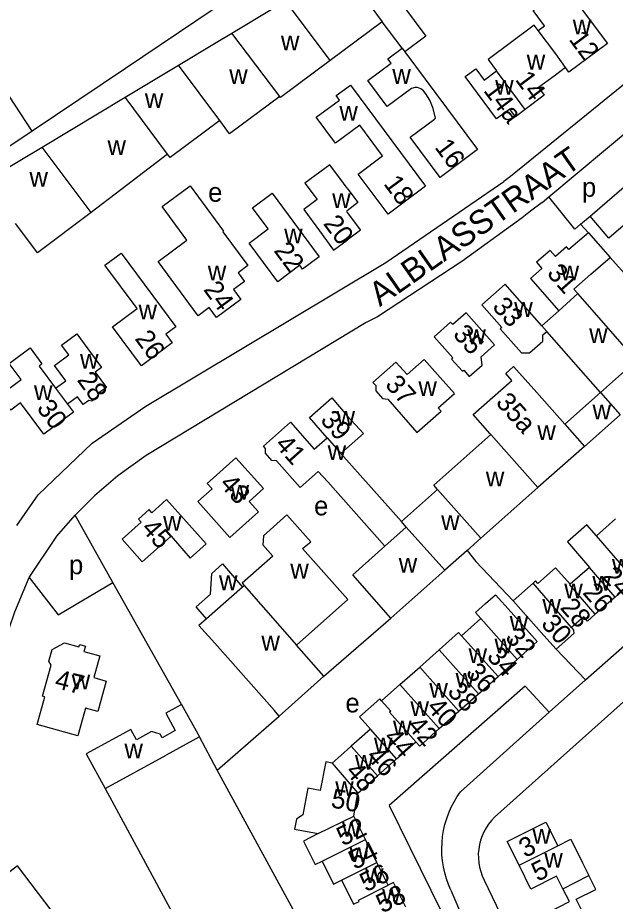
# Model space of a CAD drawing. Extents: x 156721 to 158827, y 386657 to 388950.
# Drawn here: x 157431.2 to 157555.9, y 387710.2 to 387894.5 of the extents above; entities that cross this region are included whole.
import ezdxf

# ---------------------------------------------------------------- set-up
doc = ezdxf.new("R2010")
doc.units = 0
for name, color, linetype in [('BLT_Basislijn', 7, 'Continuous'), ('BLT_Bebouwing', 7, 'Continuous'), ('BLT_Centroide', 7, 'Continuous'), ('BLT_Hoogspanningsmast_en_leidingen', 7, 'Continuous'), ('BLT_Huisnummer', 7, 'Continuous'), ('BLT_Huisnummer_ tussenligend', 7, 'Continuous'), ('BLT_Onderverdeling_panden', 7, 'Continuous'), ('BLT_Straatnaam', 7, 'Continuous')]:
    doc.layers.add(name, color=color, linetype=linetype)

msp = doc.modelspace()

# ---------------------------------------------------------------- linework, layer by layer
at = {"layer": 'BLT_Basislijn'}
for p, q in [((157542.05, 387857.12), (157567.63, 387878.57)), ((157540.64, 387855.93), (157538.26, 387854.12)), ((157540.64, 387855.93), (157542.05, 387857.12)), ((157548.7, 387851.47), (157550.68, 387853.1)), ((157550.32, 387849.62), (157548.7, 387851.47)), ((157563.41, 387834.83), (157554.84, 387844.52)), ((157549.68, 387756.41), (157593.29, 387794.87)), ((157433.63, 387777.77), (157439.68, 387769.95)), ((157439.68, 387769.95), (157451.11, 387776.75)), ((157465.46, 387751.28), (157451.11, 387776.75)), ((157495.15, 387757.16), (157509.09, 387769.3)), ((157570.53, 387763.42), (157530.74, 387727.79)), ((157549.68, 387756.41), (157543.57, 387762.81)), ((157549.68, 387756.41), (157542.13, 387749.65)), ((157472.87, 387737.57), (157485.81, 387748.88)), ((157542.13, 387749.65), (157523.63, 387733.1)), ((157521.63, 387712.57), (157524.08, 387706.86))]:
    msp.add_line(p, q, dxfattribs=at)
for points in [[(157589.35, 387906.27), (157534.05, 387861.36), (157532.64, 387860.36)], [(157431.05, 387788.63), (157435.53, 387794.97), (157446.77, 387805.76), (157457.97, 387813.49), (157508.05, 387843.42), (157531.57, 387859.59), (157532.64, 387860.36)], [(157548.7, 387851.47), (157547.46, 387850.41), (157542.05, 387857.12)], [(157538.26, 387854.12), (157536.47, 387852.76), (157523.91, 387843.64), (157506.32, 387832.11), (157503.93, 387830.93), (157458.03, 387803.21), (157452.13, 387798.96), (157447.3, 387794.79), (157443.27, 387790.75)], [(157433.63, 387777.77), (157439.41, 387786.37), (157443.27, 387790.75)], [(157451.11, 387776.75), (157443.27, 387790.75)], [(157525.01, 387783.41), (157526.82, 387781.11), (157534.63, 387772.92)], [(157448.94, 387641.7), (157448.24, 387641.22), (157437.86, 387655.06), (157417.27, 387677.44), (157412.48, 387683.06), (157411.05, 387686.03), (157410.8, 387690.3), (157412, 387696.4), (157429.48, 387767.11), (157430.68, 387770.62), (157433.63, 387777.77)], [(157542.13, 387749.65), (157537.09, 387755.14), (157508.77, 387730.24), (157526.13, 387694.91)], [(157521.63, 387712.57), (157521.13, 387713.74), (157520.71, 387714.94), (157520.36, 387716.17), (157520.08, 387717.41), (157519.89, 387718.67), (157519.77, 387719.94), (157519.74, 387721.22), (157519.78, 387722.49), (157519.91, 387723.76), (157520.11, 387725.02), (157520.39, 387726.26), (157520.75, 387727.48), (157521.19, 387728.68), (157521.7, 387729.85), (157522.28, 387730.98), (157522.93, 387732.08), (157523.63, 387733.1)], [(157530.74, 387727.79), (157530.09, 387727.1), (157529.5, 387726.36), (157528.97, 387725.57), (157528.52, 387724.74), (157528.13, 387723.87), (157527.82, 387722.98), (157527.59, 387722.06), (157527.43, 387721.12), (157527.35, 387720.18), (157527.36, 387719.23), (157527.44, 387718.29), (157527.6, 387717.36), (157527.84, 387716.44), (157528.16, 387715.55), (157528.58, 387714.63)], [(157528.58, 387714.63), (157545.48, 387679.5), (157547.3, 387675.81)]]:
    msp.add_lwpolyline(points, dxfattribs=at)
at = {"layer": 'BLT_Bebouwing'}
for p, q in [((157475.95, 387891.28), (157484.49, 387896.4)), ((157507.31, 387893.66), (157496.41, 387885.58)), ((157539, 387892.94), (157529.37, 387885.78)), ((157539.81, 387891.79), (157539, 387892.94)), ((157472.34, 387889.11), (157475.95, 387891.28)), ((157464.8, 387884.59), (157472.34, 387889.11)), ((157512.01, 387887.37), (157527.18, 387867)), ((157496.41, 387885.58), (157486.07, 387877.86)), ((157529.37, 387885.78), (157531.16, 387883.38)), ((157459.6, 387881.47), (157464.8, 387884.59)), ((157453.66, 387877.9), (157459.6, 387881.47)), ((157436.38, 387867.53), (157453.66, 387877.9)), ((157486.07, 387877.86), (157485.94, 387878.04)), ((157473.4, 387873.07), (157463.03, 387865.36)), ((157424.3, 387860.28), (157436.38, 387867.53)), ((157462.54, 387866.01), (157446.57, 387853.84)), ((157463.03, 387865.36), (157462.54, 387866.01)), ((157431.25, 387850.97), (157430.82, 387851.55)), ((157550.32, 387849.62), (157554.84, 387844.52)), ((157544.14, 387833.4), (157540.57, 387830.25)), ((157552.86, 387816.36), (157541.61, 387829.07)), ((157435.71, 387821.86), (157439.16, 387817.24)), ((157439.16, 387817.24), (157441.27, 387818.8)), ((157443.73, 387815.45), (157441.63, 387813.93)), ((157545.37, 387809.73), (157552.86, 387816.36)), ((157552.86, 387816.36), (157556.97, 387811.71)), ((157556.97, 387811.71), (157549.49, 387805.09)), ((157549.49, 387805.09), (157539.79, 387796.5)), ((157498.64, 387803.63), (157511.3, 387789.42)), ((157539.79, 387796.5), (157527.88, 387785.95)), ((157507.84, 387784.29), (157512.3, 387788.28)), ((157527.88, 387785.95), (157525.01, 387783.41)), ((157525.01, 387783.41), (157520.33, 387779.26)), ((157473.98, 387780.58), (157478.17, 387775.78)), ((157520.33, 387779.26), (157509.09, 387769.3)), ((157550.51, 387779.88), (157546.5, 387776.34)), ((157538.8, 387776.6), (157534.63, 387772.92)), ((157559.93, 387777.26), (157555.88, 387773.67)), ((157478.53, 387776.1), (157478.17, 387775.78)), ((157489.39, 387763.66), (157500.12, 387773.18)), ((157523.83, 387765.6), (157527.86, 387769.19)), ((157543.57, 387762.81), (157541.02, 387765.68)), ((157515.14, 387759.1), (157519.18, 387762.69)), ((157531.46, 387757.15), (157535.44, 387760.69)), ((157495.15, 387757.16), (157487.09, 387750)), ((157527.38, 387753.52), (157531.46, 387757.15)), ((157465.46, 387751.28), (157469.16, 387744.51)), ((157485.81, 387748.88), (157484.82, 387750)), ((157487.09, 387750), (157485.81, 387748.88)), ((157519.21, 387746.25), (157523.29, 387749.88)), ((157504.85, 387746.13), (157500.85, 387742.57)), ((157510.3, 387739.98), (157514.29, 387743.53)), ((157506.31, 387736.43), (157510.3, 387739.98)), ((157502.23, 387732.8), (157506.31, 387736.43)), ((157503.83, 387723.11), (157501.4, 387727.99)), ((157506.21, 387718.33), (157503.83, 387723.11)), ((157508.56, 387713.61), (157506.21, 387718.33))]:
    msp.add_line(p, q, dxfattribs=at)
for points in [[(157409.42, 387908.81), (157414.45, 387912.18), (157410.44, 387918.15), (157424.45, 387927.56), (157428.45, 387921.62), (157446.74, 387933.97), (157472.03, 387896.19), (157453.77, 387883.92)], [(157529.73, 387905.37), (157532.07, 387902.23), (157527.69, 387898.97), (157520.53, 387908.6), (157509.29, 387900.24), (157516.43, 387890.66), (157512.01, 387887.37)], [(157539.81, 387891.79), (157541.17, 387892.8), (157538.8, 387895.99), (157545.21, 387900.76), (157547.6, 387897.55), (157547.84, 387897.73), (157551.3, 387893.1)], [(157511.45, 387888.12), (157507.31, 387893.66)], [(157551.3, 387893.1), (157554.29, 387889.09), (157546.23, 387883.12), (157545.54, 387884.09)], [(157527.18, 387867), (157519.36, 387861.18), (157513.12, 387869.55), (157518.2, 387873.34), (157518.43, 387873.51), (157517.92, 387875.55), (157517.21, 387877.33), (157516.4, 387878.64), (157515.88, 387879.23), (157515.33, 387879.66), (157514.65, 387879.92), (157514.15, 387879.92), (157513.44, 387879.74), (157508.36, 387875.96), (157504.32, 387881.39), (157509.18, 387885.01), (157508.5, 387885.93), (157511.45, 387888.12)], [(157453.77, 387883.92), (157434.24, 387870.82)], [(157537.15, 387875.36), (157535.1, 387873.84), (157533.92, 387875.44), (157531.13, 387873.38), (157524.58, 387882.2), (157526.82, 387883.86), (157528.6, 387881.47), (157531.16, 387883.38)], [(157545.54, 387884.09), (157543.16, 387882.32), (157539.92, 387879.91), (157541.11, 387878.31), (157537.15, 387875.36)], [(157500.65, 387880.45), (157516.36, 387859.35), (157508.55, 387853.53), (157502.31, 387861.9), (157507.39, 387865.69), (157502.62, 387872.09), (157497.54, 387868.3), (157493.49, 387873.73), (157498.37, 387877.33)], [(157498.37, 387877.33), (157497.69, 387878.26), (157500.65, 387880.45)], [(157485.94, 387878.04), (157475.47, 387870.29), (157473.4, 387873.07)], [(157434.24, 387870.82), (157415.87, 387858.5)], [(157500, 387858.94), (157499.24, 387859.96), (157496.37, 387863.84), (157491.16, 387860.02), (157493.74, 387856.55), (157490.94, 387854.48), (157494.2, 387850.05), (157497.17, 387846.03), (157500, 387848.13)], [(157467.25, 387859.45), (157474.22, 387849.97), (157474.06, 387849.86), (157479.26, 387842.79), (157477.23, 387841.29), (157478.56, 387839.47), (157476.28, 387837.79), (157477.82, 387835.7), (157472.75, 387831.96), (157471.21, 387834.06), (157468.89, 387832.35), (157460.55, 387843.63), (157466.57, 387848.07), (157461.37, 387855.1), (157467.25, 387859.45)], [(157550.68, 387853.1), (157557.8, 387859.23)], [(157484.32, 387857.88), (157494.14, 387844.63), (157490.69, 387842.08), (157490.11, 387842.86), (157485.51, 387839.45), (157479.55, 387847.49), (157483.54, 387850.44), (157480.25, 387854.87), (157484.32, 387857.88)], [(157500, 387858.94), (157502.22, 387855.95), (157500, 387854.25)], [(157446.57, 387853.84), (157435.38, 387845.46), (157431.25, 387850.97)], [(157500, 387854.25), (157499.83, 387854.12), (157500, 387853.89)], [(157500, 387853.89), (157502.79, 387850.2), (157500, 387848.13)], [(157558.54, 387851.95), (157554.59, 387848.55), (157550.68, 387853.1)], [(157550.32, 387849.62), (157546.22, 387846.17), (157545.75, 387846.69), (157543.44, 387844.69)], [(157452.81, 387845.41), (157464.22, 387830.03), (157462.14, 387828.48), (157463.49, 387826.67), (157457.08, 387821.91), (157451.06, 387830.02), (157456.2, 387833.83), (157449.46, 387842.91), (157452.81, 387845.41)], [(157543.44, 387844.69), (157542.31, 387845.96), (157539.48, 387843.5), (157540.59, 387842.22), (157538.21, 387840.13), (157544.14, 387833.4)], [(157550.83, 387841.03), (157554.84, 387844.52)], [(157548.08, 387836.97), (157547.25, 387837.91), (157550.83, 387841.03)], [(157540.57, 387830.25), (157532.92, 387838.9), (157528.06, 387834.59), (157532.23, 387829.87), (157531.93, 387829.6), (157536.36, 387824.59), (157538.04, 387824.59), (157540.79, 387827.02), (157540.78, 387828.33), (157541.61, 387829.07)], [(157552.86, 387816.36), (157560.37, 387822.98), (157548.08, 387836.97)], [(157528.1, 387829.24), (157524.78, 387832.98), (157522, 387830.5), (157521.58, 387830.98), (157518.16, 387827.94), (157522.05, 387823.56), (157521.78, 387823.32), (157524.06, 387820.76), (157524.32, 387820.99), (157525.47, 387819.69), (157528.12, 387822.03), (157527.92, 387823.8), (157530.72, 387826.28), (157528.1, 387829.24)], [(157441.27, 387818.8), (157438.94, 387821.97), (157441.91, 387824.18), (157440.42, 387826.19), (157443.59, 387828.54), (157448.77, 387821.55), (157447.42, 387820.55), (157449.77, 387817.4), (157448.13, 387816.19), (157448.07, 387815.53), (157446.73, 387814.52), (157446.1, 387814.66), (157444.94, 387813.81), (157443.73, 387815.45)], [(157441.63, 387813.93), (157442.89, 387812.24), (157436.72, 387807.64), (157431.83, 387814.19), (157429.82, 387812.69), (157427.53, 387815.76), (157431.98, 387819.08), (157429.5, 387822.41), (157433.83, 387825.65), (157436.32, 387822.31), (157435.71, 387821.86)], [(157519.39, 387819.48), (157516.08, 387823.24), (157512.49, 387820.07), (157510.17, 387822.68), (157505.36, 387818.44), (157505.95, 387817.77), (157505.98, 387816.7), (157507.38, 387815.12), (157508.45, 387814.95), (157514.55, 387808.03), (157519.59, 387812.47), (157519, 387813.17), (157522.37, 387816.13), (157519.39, 387819.48)], [(157529.96, 387807.55), (157529.83, 387807.7), (157526.25, 387811.72), (157534.34, 387818.87), (157533.07, 387820.31), (157534.71, 387821.77), (157539.53, 387816.32), (157545.37, 387809.73)], [(157495.83, 387806.87), (157492.12, 387811.13), (157496.79, 387815.26), (157500, 387811.48)], [(157500, 387811.48), (157503.41, 387807.8), (157498.64, 387803.63)], [(157507.84, 387784.29), (157495.97, 387797.69), (157493.97, 387799.9), (157490.18, 387796.56), (157485.26, 387802.11), (157484.29, 387802.16), (157482.95, 387803.67), (157482.98, 387804.67), (157482.55, 387805.18), (157488.18, 387810.15), (157493.11, 387804.5), (157495.83, 387806.87)], [(157518.86, 387796.09), (157518.06, 387797), (157529.96, 387807.55)], [(157476.78, 387802.72), (157470.81, 387797.38), (157471.81, 387796.26), (157468.82, 387793.59), (157475.5, 387786.12), (157481.47, 387791.46), (157479.53, 387793.64), (157482.51, 387796.3), (157476.78, 387802.72)], [(157511.3, 387789.42), (157518.86, 387796.09)], [(157453.07, 387785.78), (157457.25, 387781.04), (157463.27, 387786.35), (157467.26, 387781.83), (157470.58, 387784.76), (157462.33, 387794.01), (157459.26, 387791.28), (157458.68, 387791.93), (157456.43, 387789.93), (157457.01, 387789.28), (157453.07, 387785.78)], [(157500.12, 387773.18), (157490.69, 387783.78), (157492.39, 387785.2), (157490.74, 387787.05), (157487.43, 387790.8), (157482.51, 387786.48), (157482.38, 387784.55), (157484.46, 387782.18), (157478.11, 387776.6), (157478.53, 387776.1)], [(157512.3, 387788.28), (157511.3, 387789.42)], [(157555.99, 387789.97), (157552.01, 387786.42)], [(157552.01, 387786.42), (157549.99, 387788.76), (157545.94, 387785.18), (157550.51, 387779.88)], [(157509.09, 387769.3), (157501.14, 387778.3), (157507.84, 387784.29)], [(157470.64, 387769.18), (157468.47, 387771.66), (157471.5, 387774.3), (157471.73, 387778.62), (157473.98, 387780.58)], [(157546.5, 387776.34), (157543.48, 387779.76), (157539.8, 387776.5), (157539.31, 387777.05), (157538.8, 387776.6)], [(157527.86, 387769.19), (157526.74, 387770.44), (157528.85, 387772.31), (157530.95, 387774.18), (157534.17, 387770.55), (157536.3, 387768.15), (157539.63, 387764.42), (157535.44, 387760.69)], [(157534.63, 387772.92), (157539.42, 387767.49), (157541.02, 387765.68)], [(157555.88, 387773.67), (157551.76, 387770.12)], [(157470.64, 387769.18), (157469.04, 387767.79), (157472.36, 387764.05), (157484.82, 387750)], [(157551.76, 387770.12), (157550.12, 387768.68), (157549.34, 387769.57), (157546.8, 387767.33)], [(157546.8, 387767.33), (157547.24, 387766.81), (157547.28, 387766.08), (157543.57, 387762.81)], [(157519.18, 387762.69), (157523.23, 387766.28), (157523.83, 387765.6)], [(157441.03, 387764.15), (157444.04, 387763.34), (157444.19, 387763.79), (157445.38, 387763.46), (157445.06, 387762.32), (157448.37, 387761.4), (157447.12, 387756.88), (157449.73, 387756.16), (157447.97, 387749.81), (157445.37, 387750.53), (157443.77, 387744.75), (157435.32, 387747.08), (157436.91, 387752.85), (157436.43, 387752.99), (157438.21, 387759.5), (157437.74, 387760.34), (157438.41, 387762.76), (157441.03, 387764.15)], [(157495.15, 387757.16), (157489.39, 387763.66)], [(157511, 387755.42), (157515.14, 387759.1)], [(157511, 387755.42), (157507.18, 387752.03)], [(157507.18, 387752.03), (157506.78, 387752.48), (157502.55, 387748.72), (157504.85, 387746.13)], [(157523.29, 387749.88), (157523.43, 387750), (157527.38, 387753.52)], [(157465.46, 387751.28), (157462.13, 387749.47), (157464.11, 387745.84), (157461.36, 387744.34), (157460.96, 387745.08), (157459.16, 387745.62), (157456.03, 387743.92), (157454.86, 387746.07), (157445.55, 387741), (157449.47, 387733.79)], [(157514.29, 387743.53), (157515.12, 387742.61), (157519.21, 387746.25)], [(157469.16, 387744.51), (157462.2, 387740.73)], [(157472.87, 387737.57), (157469.16, 387744.51)], [(157500.85, 387742.57), (157500, 387741.82), (157496.89, 387739.05)], [(157496.89, 387739.05), (157495.54, 387739.32), (157494.37, 387733.34), (157491.81, 387733.84), (157490.72, 387728.29), (157489.41, 387727.4), (157489, 387725.29), (157493.95, 387724.35)], [(157502.52, 387683.28), (157500, 387687.91), (157472.87, 387737.57)], [(157449.47, 387733.79), (157475.61, 387685.56), (157480.9, 387688.44), (157499.58, 387654.16), (157500, 387654.39), (157504.24, 387656.7), (157510.89, 387644.49)], [(157501.4, 387727.99), (157501.36, 387728.08), (157502.23, 387732.8)], [(157535.84, 387717.75), (157533.36, 387722.72), (157541.43, 387726.75), (157543.92, 387721.78)], [(157493.95, 387724.35), (157490.85, 387722.79), (157493.33, 387717.89), (157494.74, 387718.6)], [(157543.92, 387721.78), (157546.62, 387723.18), (157549.08, 387718.26), (157550.4, 387715.61)], [(157494.74, 387718.6), (157497.16, 387713.79), (157498.84, 387714.64)], [(157545.01, 387712.85), (157543.64, 387715.51), (157538.32, 387712.79), (157535.84, 387717.75)], [(157550.22, 387705.81), (157547.78, 387710.69), (157551.84, 387712.72), (157551.31, 387713.79), (157550.4, 387715.61)], [(157498.84, 387714.64), (157500, 387712.33), (157501.34, 387709.66), (157502.46, 387710.22)], [(157512.22, 387709.04), (157509.67, 387714.15), (157508.56, 387713.61)], [(157542.18, 387701.79), (157539.65, 387706.74), (157546.37, 387710.18), (157545.01, 387712.85)]]:
    msp.add_lwpolyline(points, dxfattribs=at)
at = {"layer": 'BLT_Hoogspanningsmast_en_leidingen'}
msp.add_lwpolyline([(157428.67, 387700.66), (157438.47, 387708.12), (157431.24, 387717.61), (157421.44, 387710.16)], close=True, dxfattribs=at)
at = {"layer": 'BLT_Onderverdeling_panden'}
for p, q in [((157434.24, 387870.82), (157409.42, 387908.81)), ((157498.86, 387905.05), (157507.31, 387893.66)), ((157496.41, 387885.58), (157487.14, 387897.99)), ((157485.94, 387878.04), (157475.95, 387891.28)), ((157511.45, 387888.12), (157512.01, 387887.37)), ((157473.4, 387873.07), (157464.8, 387884.59)), ((157537.15, 387875.36), (157531.16, 387883.38)), ((157462.54, 387866.01), (157453.66, 387877.9)), ((157446.57, 387853.84), (157436.38, 387867.53)), ((157544.14, 387833.4), (157548.08, 387836.97)), ((157540.57, 387830.25), (157541.61, 387829.07)), ((157439.16, 387817.24), (157441.63, 387813.93)), ((157545.37, 387809.73), (157549.49, 387805.09)), ((157495.83, 387806.87), (157498.64, 387803.63)), ((157529.96, 387807.55), (157539.79, 387796.5)), ((157518.86, 387796.09), (157527.88, 387785.95)), ((157512.3, 387788.28), (157520.33, 387779.26)), ((157559.93, 387777.26), (157552.01, 387786.42)), ((157555.88, 387773.67), (157550.51, 387779.88)), ((157546.8, 387767.33), (157538.8, 387776.6)), ((157478.17, 387775.78), (157470.64, 387769.18)), ((157478.53, 387776.1), (157489.39, 387763.66)), ((157535.44, 387760.69), (157527.86, 387769.19)), ((157531.46, 387757.15), (157523.83, 387765.6)), ((157527.38, 387753.52), (157519.18, 387762.69)), ((157523.29, 387749.88), (157515.14, 387759.1)), ((157519.21, 387746.25), (157511, 387755.42)), ((157514.29, 387743.53), (157508.82, 387749.67)), ((157510.3, 387739.98), (157504.85, 387746.13)), ((157506.31, 387736.43), (157500.85, 387742.57)), ((157449.47, 387733.79), (157462.21, 387740.73)), ((157496.89, 387739.05), (157502.23, 387732.8)), ((157493.95, 387724.35), (157501.4, 387727.99)), ((157494.74, 387718.6), (157503.83, 387723.11)), ((157535.84, 387717.75), (157543.92, 387721.78)), ((157498.84, 387714.64), (157506.21, 387718.33)), ((157545.01, 387712.85), (157550.4, 387715.61))]:
    msp.add_line(p, q, dxfattribs=at)
for points in [[(157545.54, 387884.09), (157543.49, 387886.97), (157539.81, 387891.79)], [(157551.76, 387770.12), (157546.41, 387776.24), (157546.5, 387776.34)], [(157507.18, 387752.03), (157509.08, 387749.9), (157508.82, 387749.67)], [(157502.46, 387710.22), (157502.32, 387710.49), (157508.56, 387713.61)]]:
    msp.add_lwpolyline(points, dxfattribs=at)

# ---------------------------------------------------------------- texts
at = {"layer": 'BLT_Centroide'}
for s, p in [('w', (157547.05, 387891)), ('w', (157486.17, 387887.67)), ('w', (157537.45, 387883.69)), ('w', (157475.38, 387880.67)), ('w', (157509.41, 387880.7)), ('w', (157530.86, 387878.45)), ('w', (157457.78, 387875.68)), ('w', (157498.36, 387873.04)), ('w', (157449.98, 387865.88)), ('w', (157433.7, 387859.25)), ('e', (157470.98, 387856.11)), ('p', (157548.97, 387857.15)), ('w', (157496.86, 387854.81)), ('w', (157486.84, 387847.45)), ('w', (157470.91, 387839.72)), ('w', (157544.52, 387839.72)), ('w', (157456.47, 387831.59)), ('w', (157534.84, 387832.11)), ('w', (157550.47, 387826.66)), ('w', (157525.05, 387826.41)), ('w', (157444.25, 387821.3)), ('w', (157514.85, 387815.62)), ('w', (157434.65, 387814.75)), ('w', (157551.17, 387810.72)), ('w', (157497.77, 387809.39)), ('w', (157539.66, 387806.42)), ('w', (157495.91, 387802.27)), ('w', (157528.92, 387796.75)), ('w', (157475.67, 387794)), ('e', (157493.08, 387790.72)), ('w', (157461.58, 387787.53)), ('w', (157519.59, 387787.69)), ('w', (157510.74, 387778.78)), ('p', (157441.96, 387778.44)), ('w', (157488.12, 387777.55)), ('w', (157555.23, 387778.56)), ('w', (157473.25, 387775.12)), ('w', (157545.28, 387773.41)), ('w', (157551.14, 387775.03)), ('w', (157540.72, 387770.2)), ('w', (157533.89, 387766.66)), ('w', (157482.09, 387762.53)), ('w', (157530.72, 387761.97)), ('w', (157525.31, 387759.94)), ('w', (157442.52, 387754.42)), ('w', (157522.61, 387754.77)), ('w', (157517.14, 387752.69)), ('e', (157499.62, 387749.63)), ('w', (157513.19, 387748.86)), ('w', (157509.56, 387744.83)), ('w', (157453.52, 387740.06)), ('w', (157505.58, 387741.27)), ('w', (157501.61, 387737.7)), ('w', (157497.5, 387732.2)), ('w', (157498.92, 387723.69)), ('w', (157538.64, 387722.25)), ('w', (157500.5, 387718.41)), ('w', (157541.12, 387717.28)), ('w', (157503.73, 387714.06)), ('w', (157507.27, 387709.75))]:
    msp.add_text(s, height=4, dxfattribs=at).set_placement(p)
at = {"layer": 'BLT_Huisnummer'}
for s, rotation, p in [('12', 306.5451, (157546.11, 387889.96)), ('14', 306.6173, (157534.91, 387881.57)), ('14a', 306.5956, (157528.3, 387879.28)), ('16', 306.6842, (157518.11, 387867.45)), ('18', 306.6842, (157507.45, 387859.85)), ('20', 306.6389, (157494.87, 387851.53)), ('22', 306.5577, (157484.55, 387845.9)), ('31', 311.362, (157541.49, 387841.07)), ('24', 306.3512, (157469.88, 387837.78)), ('33', 311.4674, (157530.09, 387834.1)), ('35', 311.601, (157521.88, 387828.35)), ('26', 306.5727, (157455.55, 387827.54)), ('28', 305.8221, (157443.5, 387818.93)), ('37', 311.448, (157507.73, 387817.85)), ('35a', 311.601, (157530.81, 387814.16)), ('30', 306.7269, (157435.07, 387813.05)), ('39', 311.0676, (157494.22, 387810.49)), ('41', 311.5314, (157484.76, 387805.36)), ('43', 311.787, (157473.17, 387797.15)), ('45', 311.4217, (157456.85, 387787.88)), ('24', 311.5333, (157552.95, 387777.88)), ('28', 311.4055, (157544.24, 387771.38)), ('32', 311.6625, (157532.76, 387765.12)), ('36', 311.6625, (157524.54, 387757.81)), ('47', 345.936, (157438.77, 387754.77)), ('40', 311.6672, (157516.39, 387750.55)), ('44', 311.6683, (157507.41, 387744.22)), ('48', 311.3524, (157499.46, 387737.17)), ('52', 26.5899, (157499.08, 387721.66)), ('3', 26.5367, (157537.08, 387719.24)), ('56', 26.5869, (157503.9, 387712.1))]:
    msp.add_text(s, height=4, rotation=rotation, dxfattribs=at).set_placement(p)
at = {"layer": 'BLT_Huisnummer_ tussenligend'}
for s, rotation, p in [('26', 311.3922, (157548.94, 387774.51)), ('30', 311.3922, (157540.25, 387767.99)), ('34', 311.3922, (157528.93, 387761.16)), ('38', 311.3922, (157520.71, 387753.85)), ('42', 311.3922, (157512.34, 387746.71)), ('46', 311.3922, (157503.79, 387740.35)), ('50', 349.311, (157496.42, 387729.87)), ('54', 26.5899, (157501.55, 387716.76)), ('5', 26.5367, (157539.72, 387714.28)), ('58', 26.5899, (157507.3, 387707.68))]:
    msp.add_text(s, height=4, rotation=rotation, dxfattribs=at).set_placement(p)
at = {"layer": 'BLT_Straatnaam'}
msp.add_text('ALBLASSTRAAT', height=5, rotation=34.9891, dxfattribs=at).set_placement((157506.8, 387834.14))

doc.saveas('drawing.dxf')
